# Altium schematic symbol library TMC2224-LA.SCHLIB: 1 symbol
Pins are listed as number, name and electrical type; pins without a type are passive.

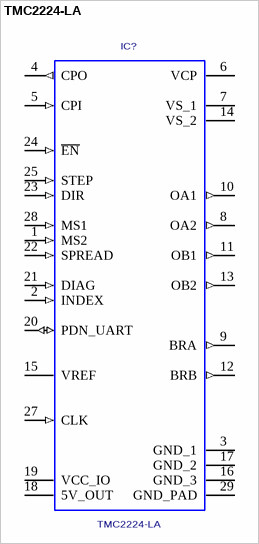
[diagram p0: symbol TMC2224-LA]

## TMC2224-LA
designator IC?
Ultra-silent Step/Dir Driver for two-Phase bipolar Stepper Motors, with Step/Dir, UART, QFN28(5x5); Manufacturer: TRINAMIC; Geometry.Height: 0.9mm; PCB DECAL: TMC_QFN28_0.5_5.0X5.0
footprint TMC_QFN28_0.5_5.0X5.0
pins: 1 MS2 (in), 2 INDEX (in), 3 GND_1 (power), 4 CPO (out), 5 CPI (in), 6 VCP (power), 7 VS_1 (power), 8 OA2 (out), 9 BRA (out), 10 OA1 (out), 11 OB1 (out), 12 BRB (out), 13 OB2 (out), 14 VS_2 (power), 15 VREF (power), 16 GND_3 (power), 17 GND_2 (power), 18 5V_OUT (power), 19 VCC_IO (power), 20 PDN_UART (io), 21 DIAG (in), 22 SPREAD (in), 23 DIR (in), 24 ~{EN} (in), 25 STEP (in), 27 CLK (in), 28 MS1 (in), 29 GND_PAD (power)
